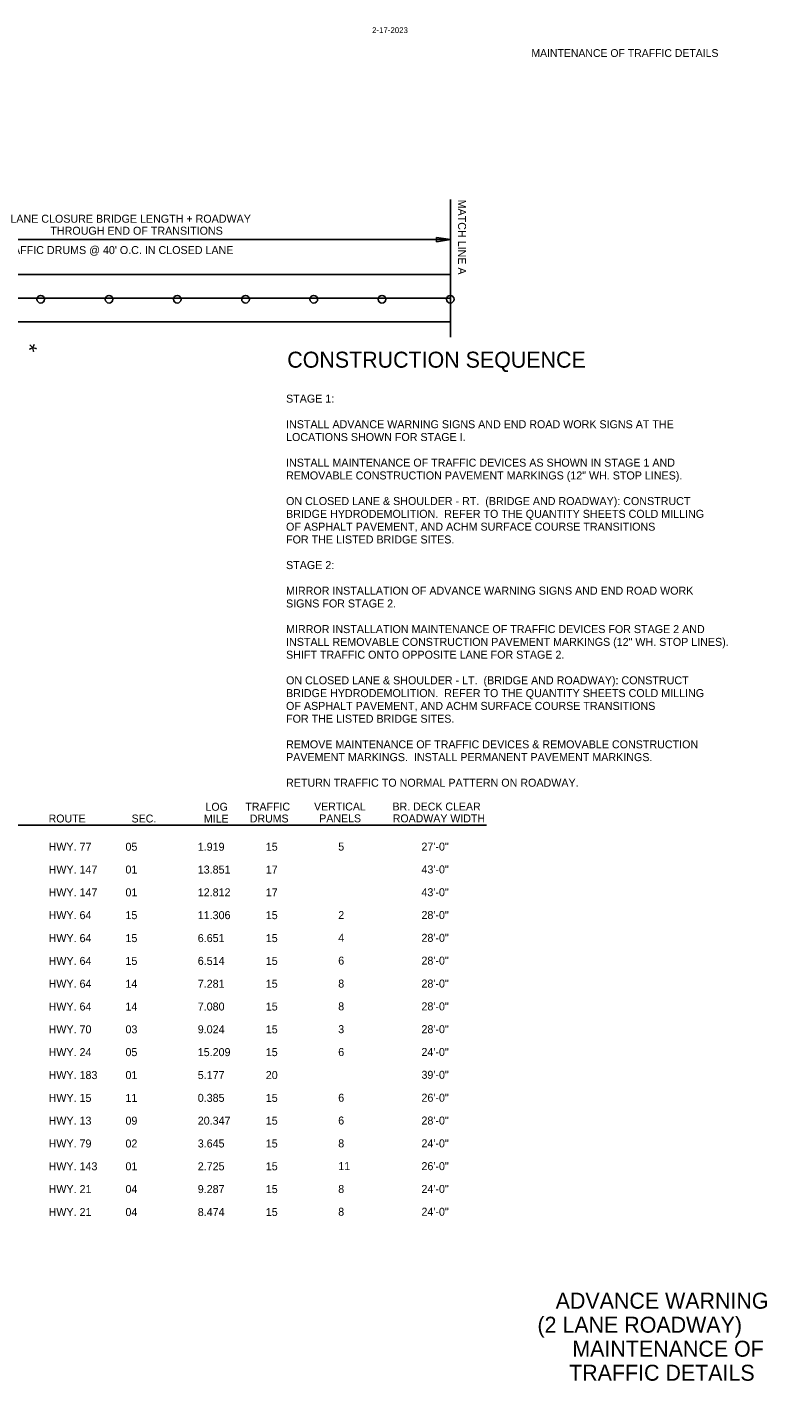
# Model space of a CAD drawing. Extents: x 1927831 to 1930787, y 596452 to 597699.
# Drawn here: x 1928856 to 1929411, y 596676 to 597691 of the extents above; entities that cross this region are included whole.
import ezdxf

# ---------------------------------------------------------------- set-up
doc = ezdxf.new("R2010")
doc.units = 0
for name, color, linetype in [('Default', 7, 'Continuous'), ('R_Border', 7, 'Continuous'), ('R_Border Prem', 7, 'Continuous')]:
    doc.layers.add(name, color=color, linetype=linetype)

msp = doc.modelspace()

# ---------------------------------------------------------------- linework, layer by layer
at = {"layer": 'Default'}
for p, q in [((1929173.7, 597561.6), (1929173.7, 597458.6)), ((1929173.7, 597531.6), (1928729.3, 597531.6)), ((1929163.2, 597530), (1929163.2, 597533.1)), ((1929163.2, 597533.1), (1929173.7, 597531.6)), ((1929173.7, 597531.6), (1929163.2, 597530)), ((1928044.8, 597505.6), (1929173.7, 597505.6)), ((1927908.3, 597487.8), (1929173.7, 597487.8)), ((1928044.8, 597470), (1929173.7, 597470))]:
    msp.add_line(p, q, dxfattribs=at)
for centre in [(1928866.5, 597486.9), (1928917.7, 597486.9), (1928968.8, 597486.9), (1929020, 597486.9), (1929071.2, 597486.9), (1929122.3, 597486.9), (1929173.5, 597486.9)]:
    msp.add_circle(centre, 2.88, dxfattribs=at)
at = {"layer": 'R_Border'}
msp.add_line((1928746, 597092.7), (1929200.7, 597092.7), dxfattribs=at)

# ---------------------------------------------------------------- texts
at = {"layer": 'Default'}
for s, rotation, p in [('MATCH LINE A', 270, (1929179.3, 597561.6)), ('LANE CLOSURE BRIDGE LENGTH + ROADWAY ', 360, (1928843.7, 597544.3)), ('THROUGH END OF TRANSITIONS', 360, (1928873.7, 597535.3)), ("TRAFFIC DRUMS @ 40' O.C. IN CLOSED LANE", 360, (1928835, 597520.8))]:
    msp.add_text(s, height=6, rotation=rotation, dxfattribs=at).set_placement(p)
at = {"layer": 'R_Border'}
for s, height, rotation, p in [('*', 12, 45, (1928864.5, 597442.1)), ('CONSTRUCTION SEQUENCE', 12, 360, (1929051.3, 597435.6)), ('STAGE 1:', 6, 360, (1929050.4, 597409.4)), ('INSTALL ADVANCE WARNING SIGNS AND END ROAD WORK SIGNS AT THE', 6, 360, (1929050.4, 597390.2)), ('LOCATIONS SHOWN FOR STAGE I.  ', 6, 360, (1929050.4, 597380.6)), ('INSTALL MAINTENANCE OF TRAFFIC DEVICES AS SHOWN IN STAGE 1 AND', 6, 360, (1929050.4, 597361.4)), ('REMOVABLE CONSTRUCTION PAVEMENT MARKINGS (12" WH. STOP LINES). ', 6, 360, (1929050.4, 597351.8)), ('ON CLOSED LANE & SHOULDER - RT.  (BRIDGE AND ROADWAY): CONSTRUCT', 6, 360, (1929050.4, 597332.6)), ('BRIDGE HYDRODEMOLITION.  REFER TO THE QUANTITY SHEETS COLD MILLING', 6, 360, (1929050.4, 597323)), ('OF ASPHALT PAVEMENT, AND ACHM SURFACE COURSE TRANSITIONS', 6, 360, (1929050.4, 597313.4)), ('FOR THE LISTED BRIDGE SITES.', 6, 360, (1929050.4, 597303.8)), ('STAGE 2:', 6, 360, (1929050.4, 597284.6)), ('MIRROR INSTALLATION OF ADVANCE WARNING SIGNS AND END ROAD WORK', 6, 360, (1929050.4, 597265.4)), ('SIGNS FOR STAGE 2.  ', 6, 360, (1929050.4, 597255.8)), ('MIRROR INSTALLATION MAINTENANCE OF TRAFFIC DEVICES FOR STAGE 2 AND', 6, 360, (1929050.4, 597236.6)), ('INSTALL REMOVABLE CONSTRUCTION PAVEMENT MARKINGS (12" WH. STOP LINES).', 6, 360, (1929050.4, 597227)), ('SHIFT TRAFFIC ONTO OPPOSITE LANE FOR STAGE 2.', 6, 360, (1929050.4, 597217.4)), ('ON CLOSED LANE & SHOULDER - LT.  (BRIDGE AND ROADWAY): CONSTRUCT', 6, 360, (1929050.4, 597198.2)), ('BRIDGE HYDRODEMOLITION.  REFER TO THE QUANTITY SHEETS COLD MILLING', 6, 360, (1929050.4, 597188.6)), ('OF ASPHALT PAVEMENT, AND ACHM SURFACE COURSE TRANSITIONS', 6, 360, (1929050.4, 597179)), ('FOR THE LISTED BRIDGE SITES.', 6, 360, (1929050.4, 597169.4)), ('REMOVE MAINTENANCE OF TRAFFIC DEVICES & REMOVABLE CONSTRUCTION', 6, 360, (1929050.4, 597150.2)), ('PAVEMENT MARKINGS.  INSTALL PERMANENT PAVEMENT MARKINGS.', 6, 360, (1929050.4, 597140.6)), ('RETURN TRAFFIC TO NORMAL PATTERN ON ROADWAY. ', 6, 360, (1929050.4, 597121.4)), ('LOG', 5.93, 360, (1928990, 597103.4)), ('TRAFFIC ', 5.93, 360, (1929019.9, 597103.5)), ('VERTICAL', 5.93, 360, (1929071.4, 597103.6)), ('BR. DECK CLEAR', 5.929, 360, (1929130.2, 597103.6)), ('ROUTE', 5.93, 360, (1928872.4, 597094.6)), ('SEC.', 5.93, 360, (1928934.6, 597094.6)), ('MILE', 5.93, 360, (1928988.8, 597094.5)), ('DRUMS', 5.93, 360, (1929023.2, 597094.6)), ('PANELS', 5.93, 360, (1929075.3, 597094.7)), ('ROADWAY WIDTH', 5.929, 360, (1929130.4, 597094.7)), ('ADVANCE WARNING', 12, 360, (1929252.5, 596730)), (' (2 LANE ROADWAY) ', 12, 360, (1929234.4, 596712)), ('MAINTENANCE OF ', 12, 360, (1929265, 596694)), ('TRAFFIC DETAILS', 12, 360, (1929262.6, 596676))]:
    msp.add_text(s, height=height, rotation=rotation, dxfattribs=at).set_placement(p)
for s, p in [('HWY. 77', (1928872.4, 597073.4)), ('05', (1928930, 597073.4)), ('1.919', (1928984.2, 597073.4)), ('15', (1929035.2, 597073.4)), ('5', (1929089.5, 597073.5)), ('27\'-0"', (1929151.9, 597073.5)), ('HWY. 147', (1928872.4, 597056.3)), ('01', (1928930, 597056.3)), ('13.851', (1928984.2, 597056.3)), ('17', (1929035.2, 597056.3)), ('43\'-0"', (1929151.9, 597056.4)), ('HWY. 147', (1928872.4, 597039.2)), ('01', (1928930, 597039.2)), ('12.812', (1928984.2, 597039.2)), ('17', (1929035.2, 597039.2)), ('43\'-0"', (1929151.9, 597039.3)), ('HWY. 64', (1928872.4, 597022.1)), ('15', (1928930, 597022.1)), ('11.306', (1928984.2, 597022.1)), ('15', (1929035.2, 597022.1)), ('2', (1929089.5, 597022.2)), ('28\'-0"', (1929151.9, 597022.2)), ('HWY. 64', (1928872.4, 597004.9)), ('15', (1928930, 597004.9)), ('6.651', (1928984.2, 597004.9)), ('15', (1929035.2, 597004.9)), ('4', (1929089.5, 597005.1)), ('28\'-0"', (1929151.9, 597005.1)), ('HWY. 64', (1928872.4, 596987.8)), ('15', (1928930, 596987.8)), ('6.514', (1928984.2, 596987.8)), ('15', (1929035.2, 596987.8)), ('6', (1929089.5, 596988)), ('28\'-0"', (1929151.9, 596988)), ('HWY. 64', (1928872.4, 596970.7)), ('14', (1928930, 596970.7)), ('7.281', (1928984.2, 596970.7)), ('15', (1929035.2, 596970.7)), ('8', (1929089.5, 596970.8)), ('28\'-0"', (1929151.9, 596970.8)), ('HWY. 64', (1928872.4, 596953.6)), ('14', (1928930, 596953.6)), ('7.080', (1928984.2, 596953.6)), ('15', (1929035.2, 596953.6)), ('8', (1929089.5, 596953.7)), ('28\'-0"', (1929151.9, 596953.7)), ('HWY. 70', (1928872.4, 596936.5)), ('03', (1928930, 596936.5)), ('9.024', (1928984.2, 596936.5)), ('15', (1929035.2, 596936.5)), ('3', (1929089.5, 596936.6)), ('28\'-0"', (1929151.9, 596936.6)), ('HWY. 24', (1928872.4, 596919.4)), ('05', (1928930, 596919.4)), ('15.209', (1928984.2, 596919.4)), ('15', (1929035.2, 596919.4)), ('6', (1929089.5, 596919.5)), ('24\'-0"', (1929151.9, 596919.5)), ('HWY. 183', (1928872.4, 596902.2)), ('01', (1928930, 596902.2)), ('5.177', (1928984.2, 596902.2)), ('20', (1929035.2, 596902.2)), ('39\'-0"', (1929151.9, 596902.4)), ('HWY. 15', (1928872.4, 596885.1)), ('11', (1928930, 596885.1)), ('0.385', (1928984.2, 596885.1)), ('15', (1929035.2, 596885.1)), ('6', (1929089.5, 596885.2)), ('26\'-0"', (1929151.9, 596885.2)), ('HWY. 13', (1928872.4, 596868)), ('09', (1928930, 596868)), ('20.347', (1928984.2, 596868)), ('15', (1929035.2, 596868)), ('6', (1929089.5, 596868.1)), ('28\'-0"', (1929151.9, 596868.1)), ('HWY. 79', (1928872.4, 596850.9)), ('02', (1928930, 596850.9)), ('3.645', (1928984.2, 596850.9)), ('15', (1929035.2, 596850.9)), ('8', (1929089.5, 596851)), ('24\'-0"', (1929151.9, 596851)), ('HWY. 143', (1928872.4, 596833.8)), ('01', (1928930, 596833.8)), ('2.725', (1928984.2, 596833.8)), ('15', (1929035.2, 596833.8)), ('11', (1929089.5, 596833.9)), ('26\'-0"', (1929151.9, 596833.9)), ('HWY. 21', (1928872.4, 596816.7)), ('04', (1928930, 596816.7)), ('9.287', (1928984.2, 596816.7)), ('15', (1929035.2, 596816.7)), ('8', (1929089.5, 596816.8)), ('24\'-0"', (1929151.9, 596816.8)), ('HWY. 21', (1928872.4, 596799.5)), ('04', (1928930, 596799.5)), ('8.474', (1928984.2, 596799.5)), ('15', (1929035.2, 596799.5)), ('8', (1929089.5, 596799.7)), ('24\'-0"', (1929151.9, 596799.7))]:
    msp.add_text(s, height=6, dxfattribs=at).set_placement(p)
at = {"layer": 'R_Border Prem'}
msp.add_text('2-17-2023', height=4.4, dxfattribs=at).set_placement((1929114.9, 597686.5))
msp.add_text('MAINTENANCE OF TRAFFIC DETAILS', height=5.862, rotation=360, dxfattribs=at).set_placement((1929234.3, 597668.6))

doc.saveas('drawing.dxf')
